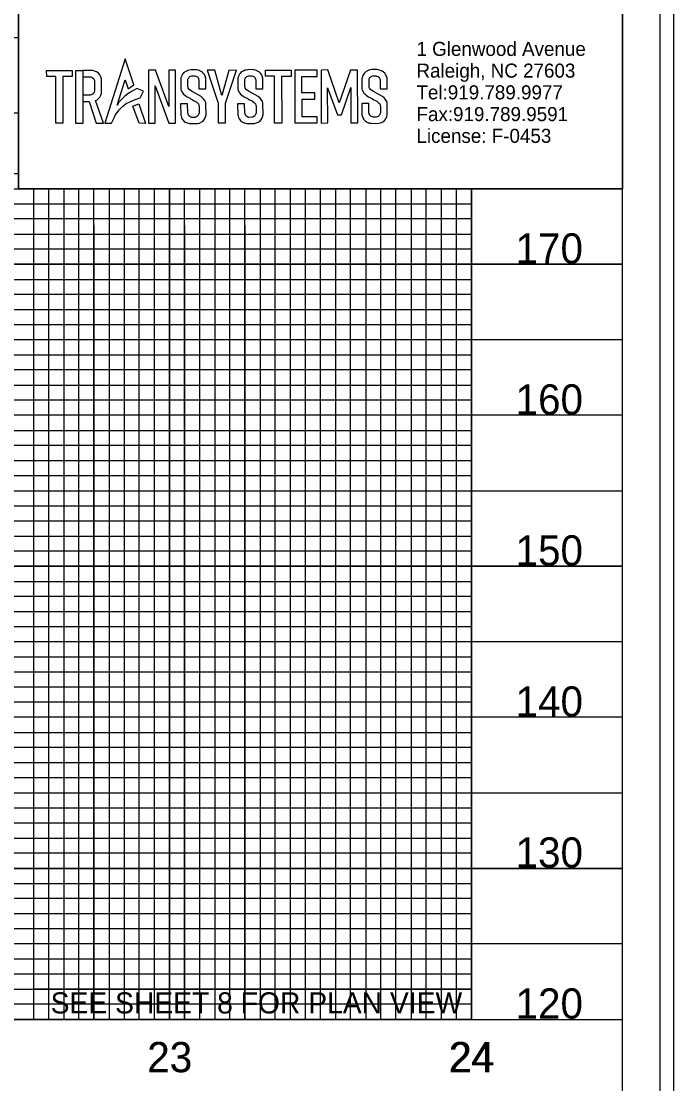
# Model space of a CAD drawing. Extents: x 1779926 to 1781610, y 605564 to 621564.
# Drawn here: x 1781393.9 to 1781610, y 606117.9 to 606469.7 of the extents above; entities that cross this region are included whole.
import ezdxf

# ---------------------------------------------------------------- set-up
doc = ezdxf.new("R2010")
doc.units = 0
for name, color, linetype in [('Exist Vertical Profile Horizontal Axis Label Major', 7, 'Continuous'), ('Exist Vertical Profile Vertical Axis Label', 7, 'Continuous'), ('Old_Level_2', 7, 'Continuous'), ('Old_Level_58', 7, 'Continuous'), ('Prop DSN Text', 7, 'Continuous'), ('Prop Grid Mask', 7, 'Continuous'), ('Scratch_Level_0', 7, 'Continuous'), ('Sheet DOT Grid CELL', 7, 'Continuous'), ('Sheet Layout Profile Border Port 1', 7, 'Continuous'), ('Sheet Plot Border Inside CELL', 7, 'Continuous'), ('Sheet Plot Border Outside CELL', 7, 'Continuous'), ('Sheet Profile CELL', 7, 'Continuous'), ('Sheet Profile Grid Major CELL', 7, 'Continuous'), ('Sheet Profile Grid Middle CELL', 7, 'Continuous'), ('Sheet Profile Grid Minor CELL', 7, 'Continuous')]:
    doc.layers.add(name, color=color, linetype=linetype)

msp = doc.modelspace()

# ---------------------------------------------------------------- linework, layer by layer
at = {"layer": 'Old_Level_2'}
for points in [[(1781428.25, 606457.24), (1781421.58, 606435.9), (1781423.81, 606435.91), (1781424.15, 606436.75), (1781424.72, 606437.91), (1781425.03, 606438.54), (1781425.41, 606439.08), (1781425.93, 606439.84), (1781426.26, 606440.31), (1781426.64, 606440.7), (1781427.02, 606441.09), (1781427.51, 606441.59), (1781427.92, 606441.86), (1781428.33, 606442.19), (1781428.89, 606442.51), (1781429.38, 606442.79), (1781430.6, 606443.36), (1781431.6, 606443.77), (1781433.24, 606444.33), (1781434.38, 606446.47), (1781432.2, 606447.43), (1781430.57, 606446.54), (1781429.19, 606445.64), (1781428.21, 606444.84), (1781427.69, 606444.42), (1781427.15, 606443.85), (1781426.62, 606443.28), (1781426.22, 606442.86), (1781425.84, 606442.21), (1781425.63, 606441.85), (1781428.26, 606450.23), (1781429.26, 606447.34), (1781431.16, 606448.59)], [(1781402.29, 606453.39), (1781410.75, 606453.4), (1781410.75, 606451.32), (1781407.64, 606451.32), (1781407.66, 606435.9), (1781405.31, 606435.9), (1781405.29, 606451.42), (1781402.32, 606451.42)], [(1781411.91, 606453.38), (1781414.22, 606453.39), (1781414.24, 606435.82), (1781411.92, 606435.82)], [(1781414.22, 606451.3), (1781416.61, 606451.3), (1781416.91, 606451.25), (1781417.32, 606451.09), (1781417.64, 606450.87), (1781417.87, 606450.6), (1781418.03, 606450.27), (1781418.15, 606450.01), (1781418.15, 606449.43), (1781418.16, 606446.94), (1781418.1, 606446.61), (1781418.01, 606446.17), (1781417.88, 606445.87), (1781417.68, 606445.61), (1781417.41, 606445.4), (1781416.99, 606445.25), (1781416.66, 606445.2), (1781416.34, 606445.16), (1781414.23, 606445.15), (1781414.24, 606443.04), (1781416.35, 606443.06), (1781418.72, 606435.89), (1781421.13, 606435.92), (1781418.48, 606443.46), (1781418.86, 606443.59), (1781419.4, 606443.99), (1781419.89, 606444.53), (1781420.23, 606445.16), (1781420.45, 606445.79), (1781420.43, 606445.98), (1781420.48, 606450.54), (1781420.27, 606451.29), (1781419.91, 606451.97), (1781419.5, 606452.44), (1781418.8, 606452.91), (1781418.12, 606453.14), (1781417.45, 606453.36), (1781417.04, 606453.36), (1781414.22, 606453.39)], [(1781436.02, 606453.42), (1781436.03, 606435.96), (1781438.27, 606435.96), (1781438.26, 606448.24), (1781442.71, 606435.94), (1781444.96, 606435.97), (1781444.94, 606453.47), (1781442.76, 606453.47), (1781442.78, 606441.49), (1781438.37, 606453.43)], [(1781452.72, 606447.25), (1781455.03, 606447.25), (1781455.02, 606450.73), (1781454.83, 606451.43), (1781454.55, 606452.02), (1781454.25, 606452.41), (1781453.88, 606452.77), (1781453.44, 606453.05), (1781453.01, 606453.22), (1781453.01, 606453.22), (1781452.55, 606453.42), (1781452.07, 606453.54), (1781451.75, 606453.62), (1781450, 606453.58), (1781449.47, 606453.49), (1781449.02, 606453.41), (1781448.55, 606453.17), (1781448.15, 606452.96), (1781447.76, 606452.68), (1781447.45, 606452.36), (1781447.2, 606452), (1781447.01, 606451.6), (1781446.75, 606450.91), (1781446.7, 606450.39), (1781446.7, 606447.22), (1781446.82, 606446.75), (1781447.05, 606446.25), (1781447.34, 606445.84), (1781447.63, 606445.53), (1781448.08, 606445.18), (1781448.54, 606444.84), (1781448.82, 606444.62), (1781449.3, 606444.39), (1781449.79, 606444.17), (1781450.18, 606443.91), (1781450.62, 606443.63), (1781451.15, 606443.36), (1781451.58, 606443.14), (1781452.01, 606442.83), (1781452.32, 606442.53), (1781452.57, 606442.29), (1781452.72, 606441.81), (1781452.82, 606441.51), (1781452.78, 606439.28), (1781452.62, 606438.79), (1781452.38, 606438.37), (1781452.05, 606438.08), (1781451.69, 606437.92), (1781451.35, 606437.85), (1781450.39, 606437.83), (1781450.07, 606437.92), (1781449.74, 606438.11), (1781449.41, 606438.31), (1781449.27, 606438.64), (1781449.13, 606438.98), (1781449.01, 606439.24), (1781448.98, 606442.36), (1781446.64, 606442.33), (1781446.68, 606438.62), (1781446.8, 606438.34), (1781447.07, 606437.47), (1781447.24, 606437.18), (1781447.5, 606436.86), (1781447.88, 606436.49), (1781448.18, 606436.3), (1781448.62, 606436.11), (1781448.78, 606436.05), (1781449.2, 606435.87), (1781449.74, 606435.81), (1781450.13, 606435.77), (1781452.27, 606435.83), (1781452.87, 606435.97), (1781453.69, 606436.34), (1781453.97, 606436.47), (1781454.6, 606437.26), (1781454.93, 606438.05), (1781455.08, 606438.76), (1781455.03, 606442.18), (1781455.02, 606442.65), (1781454.89, 606443.03), (1781454.7, 606443.38), (1781454.16, 606444.14), (1781453.45, 606444.7), (1781452.48, 606445.28), (1781451.73, 606445.72), (1781450.27, 606446.49), (1781449.52, 606447.05), (1781449.19, 606447.47), (1781449.11, 606447.75), (1781449.03, 606448.04), (1781449.08, 606450.47), (1781449.2, 606450.72), (1781449.33, 606450.98), (1781449.51, 606451.13), (1781449.74, 606451.33), (1781450, 606451.43), (1781450.25, 606451.54), (1781450.4, 606451.51), (1781450.42, 606451.59), (1781451.38, 606451.57), (1781451.65, 606451.46), (1781451.93, 606451.35), (1781452.21, 606451.24), (1781452.34, 606451.05), (1781452.52, 606450.77), (1781452.61, 606450.49), (1781452.71, 606450.22), (1781452.7, 606449.91)], [(1781457.99, 606453.43), (1781455.45, 606453.43), (1781459.07, 606442.55), (1781459.1, 606436), (1781461.49, 606436.02), (1781461.46, 606442.51), (1781465.12, 606453.47), (1781462.62, 606453.4), (1781460.31, 606445.06)], [(1781471.59, 606447.27), (1781473.9, 606447.27), (1781473.89, 606450.75), (1781473.7, 606451.45), (1781473.42, 606452.04), (1781473.12, 606452.43), (1781472.75, 606452.78), (1781472.31, 606453.07), (1781471.88, 606453.24), (1781471.88, 606453.24), (1781471.43, 606453.43), (1781470.94, 606453.56), (1781470.62, 606453.64), (1781468.87, 606453.6), (1781468.34, 606453.51), (1781467.89, 606453.43), (1781467.43, 606453.19), (1781467.02, 606452.98), (1781466.63, 606452.69), (1781466.32, 606452.38), (1781466.08, 606452.02), (1781465.88, 606451.62), (1781465.63, 606450.92), (1781465.58, 606450.41), (1781465.58, 606447.24), (1781465.69, 606446.76), (1781465.92, 606446.27), (1781466.21, 606445.86), (1781466.51, 606445.55), (1781466.96, 606445.2), (1781467.41, 606444.85), (1781467.69, 606444.63), (1781468.18, 606444.41), (1781468.66, 606444.18), (1781469.05, 606443.93), (1781469.49, 606443.64), (1781470.02, 606443.38), (1781470.45, 606443.16), (1781470.88, 606442.84), (1781471.19, 606442.55), (1781471.44, 606442.31), (1781471.59, 606441.83), (1781471.69, 606441.53), (1781471.65, 606439.29), (1781471.49, 606438.81), (1781471.25, 606438.39), (1781470.92, 606438.1), (1781470.56, 606437.94), (1781470.22, 606437.87), (1781469.26, 606437.85), (1781468.94, 606437.94), (1781468.61, 606438.13), (1781468.28, 606438.32), (1781468.14, 606438.66), (1781468, 606438.99), (1781467.88, 606439.26), (1781467.85, 606442.37), (1781465.51, 606442.35), (1781465.55, 606438.64), (1781465.67, 606438.35), (1781465.94, 606437.49), (1781466.12, 606437.2), (1781466.37, 606436.88), (1781466.75, 606436.51), (1781467.05, 606436.31), (1781467.49, 606436.13), (1781467.65, 606436.06), (1781468.08, 606435.88), (1781468.61, 606435.83), (1781469, 606435.79), (1781471.15, 606435.84), (1781471.74, 606435.99), (1781472.57, 606436.36), (1781472.85, 606436.49), (1781473.47, 606437.28), (1781473.8, 606438.06), (1781473.96, 606438.77), (1781473.9, 606442.2), (1781473.9, 606442.67), (1781473.76, 606443.04), (1781473.57, 606443.4), (1781473.03, 606444.16), (1781472.33, 606444.71), (1781471.35, 606445.29), (1781470.61, 606445.74), (1781469.14, 606446.5), (1781468.39, 606447.07), (1781468.06, 606447.49), (1781467.98, 606447.77), (1781467.91, 606448.06), (1781467.95, 606450.49), (1781468.08, 606450.74), (1781468.2, 606451), (1781468.38, 606451.15), (1781468.61, 606451.34), (1781468.87, 606451.45), (1781469.13, 606451.56), (1781469.27, 606451.53), (1781469.29, 606451.6), (1781470.25, 606451.59), (1781470.52, 606451.48), (1781470.8, 606451.37), (1781471.08, 606451.26), (1781471.21, 606451.07), (1781471.39, 606450.79), (1781471.49, 606450.51), (1781471.58, 606450.24), (1781471.57, 606449.93)], [(1781474.74, 606453.46), (1781483.21, 606453.46), (1781483.21, 606451.39), (1781480.1, 606451.39), (1781480.12, 606435.97), (1781477.77, 606435.96), (1781477.75, 606451.49), (1781474.78, 606451.49)], [(1781491.82, 606453.46), (1781484.43, 606453.46), (1781484.45, 606436.03), (1781491.92, 606436.04), (1781491.92, 606438.01), (1781486.87, 606438), (1781486.87, 606443.85), (1781491.08, 606443.85), (1781491.08, 606445.92), (1781486.83, 606445.92), (1781486.83, 606451.42), (1781491.84, 606451.42)], [(1781499.19, 606442.61), (1781495.38, 606453.54), (1781493.17, 606453.43), (1781493.25, 606435.97), (1781495.36, 606435.98), (1781495.31, 606447.66), (1781498.57, 606438.67), (1781499.92, 606438.64), (1781502.99, 606447.77), (1781503.03, 606436.05), (1781505.32, 606436.06), (1781505.25, 606453.48), (1781502.95, 606453.47)], [(1781512.72, 606447.31), (1781515.03, 606447.31), (1781515.03, 606450.78), (1781514.83, 606451.49), (1781514.55, 606452.08), (1781514.25, 606452.47), (1781513.88, 606452.82), (1781513.44, 606453.1), (1781513.02, 606453.28), (1781513.02, 606453.28), (1781512.56, 606453.47), (1781512.08, 606453.59), (1781511.76, 606453.67), (1781510.01, 606453.64), (1781509.48, 606453.55), (1781509.02, 606453.47), (1781508.56, 606453.23), (1781508.15, 606453.02), (1781507.76, 606452.73), (1781507.45, 606452.42), (1781507.21, 606452.05), (1781507.01, 606451.66), (1781506.76, 606450.96), (1781506.71, 606450.45), (1781506.71, 606447.28), (1781506.82, 606446.8), (1781507.05, 606446.31), (1781507.34, 606445.9), (1781507.64, 606445.59), (1781508.09, 606445.24), (1781508.54, 606444.89), (1781508.83, 606444.67), (1781509.31, 606444.45), (1781509.79, 606444.22), (1781510.18, 606443.97), (1781510.62, 606443.68), (1781511.15, 606443.42), (1781511.58, 606443.2), (1781512.01, 606442.88), (1781512.32, 606442.59), (1781512.57, 606442.35), (1781512.73, 606441.87), (1781512.82, 606441.57), (1781512.79, 606439.33), (1781512.62, 606438.85), (1781512.38, 606438.43), (1781512.05, 606438.14), (1781511.7, 606437.98), (1781511.36, 606437.91), (1781510.39, 606437.89), (1781510.07, 606437.98), (1781509.74, 606438.17), (1781509.41, 606438.36), (1781509.27, 606438.7), (1781509.13, 606439.03), (1781509.02, 606439.3), (1781508.98, 606442.41), (1781506.64, 606442.38), (1781506.69, 606438.67), (1781506.8, 606438.39), (1781507.07, 606437.53), (1781507.25, 606437.24), (1781507.5, 606436.92), (1781507.88, 606436.54), (1781508.19, 606436.35), (1781508.62, 606436.17), (1781508.78, 606436.1), (1781509.21, 606435.92), (1781509.74, 606435.87), (1781510.14, 606435.83), (1781512.28, 606435.88), (1781512.87, 606436.02), (1781513.7, 606436.4), (1781513.98, 606436.52), (1781514.6, 606437.32), (1781514.93, 606438.1), (1781515.09, 606438.81), (1781515.04, 606442.23), (1781515.03, 606442.71), (1781514.9, 606443.08), (1781514.71, 606443.44), (1781514.17, 606444.2), (1781513.46, 606444.75), (1781512.48, 606445.33), (1781511.74, 606445.78), (1781510.28, 606446.54), (1781509.52, 606447.1), (1781509.19, 606447.53), (1781509.12, 606447.81), (1781509.04, 606448.09), (1781509.08, 606450.52), (1781509.21, 606450.78), (1781509.33, 606451.03), (1781509.51, 606451.19), (1781509.74, 606451.38), (1781510, 606451.49), (1781510.26, 606451.6), (1781510.41, 606451.57), (1781510.42, 606451.64), (1781511.38, 606451.63), (1781511.66, 606451.52), (1781511.93, 606451.41), (1781512.21, 606451.3), (1781512.34, 606451.1), (1781512.53, 606450.83), (1781512.62, 606450.55), (1781512.71, 606450.27), (1781512.7, 606449.97)], [(1781430.86, 606441.53), (1781432.78, 606442.3), (1781435.04, 606435.86), (1781432.94, 606435.94)]]:
    msp.add_lwpolyline(points, close=True, dxfattribs=at)
at = {"layer": 'Old_Level_58'}
msp.add_lwpolyline([(1781392.96, 606478.15), (1781592.95, 606478.15), (1781592.95, 606414.2), (1781392.96, 606414.2)], close=True, dxfattribs=at)
at = {"layer": 'Prop Grid Mask'}
msp.add_lwpolyline([(1781542.96, 606149.2), (1781397.96, 606149.2), (1781397.96, 606139.2), (1781542.96, 606139.2)], close=True, dxfattribs=at)
at = {"layer": 'Scratch_Level_0'}
msp.add_lwpolyline([(1780142.96, 606139.19), (1780142.96, 606639.19), (1781392.96, 606639.19), (1781392.96, 606414.19), (1781542.96, 606414.19), (1781542.96, 606139.19)], close=True, dxfattribs=at)
at = {"layer": 'Sheet DOT Grid CELL'}
for p, q in [((1781442.96, 606139.2), (1781442.96, 606414.2)), ((1781492.96, 606139.2), (1781492.96, 606414.2)), ((1781542.96, 606139.2), (1781542.96, 606414.2)), ((1781592.96, 606389.2), (1780092.96, 606389.2)), ((1781592.96, 606339.2), (1780092.96, 606339.2)), ((1781592.96, 606289.2), (1780092.96, 606289.2)), ((1781592.96, 606239.2), (1780092.96, 606239.2)), ((1781592.96, 606189.2), (1780092.96, 606189.2))]:
    msp.add_line(p, q, dxfattribs=at)
at = {"layer": 'Sheet Layout Profile Border Port 1'}
msp.add_lwpolyline([(1780142.96, 606639.19), (1781392.91, 606639.2), (1781392.9, 606414.2), (1781542.96, 606414.19), (1781542.96, 606139.2), (1780142.96, 606139.19)], close=True, dxfattribs=at)
msp.add_lwpolyline([(1780142.96, 606478.15), (1780142.96, 606139.2), (1781542.96, 606139.2), (1781542.96, 606414.2)], dxfattribs=at)
at = {"layer": 'Sheet Plot Border Inside CELL'}
msp.add_lwpolyline([(1779938.96, 605586.65), (1781605.46, 605586.65), (1781605.46, 606641.75), (1779938.96, 606641.75)], close=True, dxfattribs=at)
at = {"layer": 'Sheet Plot Border Outside CELL'}
msp.add_lwpolyline([(1779925.96, 605564.2), (1781609.96, 605564.2), (1781609.96, 606664.2), (1779925.96, 606664.2)], close=True, dxfattribs=at)
at = {"layer": 'Sheet Profile CELL'}
msp.add_line((1780092.96, 606139.2), (1781592.96, 606139.2), dxfattribs=at)
msp.add_lwpolyline([(1781592.96, 606639.2), (1780092.96, 606639.2), (1780092.96, 605589.2), (1781592.96, 605589.2)], close=True, dxfattribs=at)
at = {"layer": 'Sheet Profile Grid Major CELL'}
for points in [[(1781542.96, 606414.2), (1781542.96, 606139.2), (1781592.96, 606139.2), (1781592.96, 606489.2)], [(1781392.91, 606439.2), (1780092.96, 606439.2), (1780092.96, 606389.2), (1781592.96, 606389.2)], [(1781442.96, 606414.2), (1781442.96, 606139.2), (1781492.96, 606139.2), (1781492.96, 606139.2), (1781492.96, 606414.2)], [(1781592.96, 606339.2), (1780092.96, 606339.2), (1780092.96, 606289.2), (1781592.96, 606289.2)], [(1781592.96, 606239.2), (1780092.96, 606239.2), (1780092.96, 606239.2), (1780092.96, 606189.2), (1781592.96, 606189.2)]]:
    msp.add_lwpolyline(points, dxfattribs=at)
at = {"layer": 'Sheet Profile Grid Middle CELL'}
for points in [[(1780917.96, 606639.2), (1780967.96, 606639.2), (1780967.96, 606139.2), (1781017.96, 606139.2), (1781017.96, 606639.2), (1781067.96, 606639.2), (1781067.96, 606139.2), (1781117.96, 606139.2), (1781117.96, 606639.2), (1781167.96, 606639.2), (1781167.96, 606139.2), (1781217.96, 606139.2), (1781217.96, 606639.2), (1781267.96, 606639.2), (1781267.96, 606139.2), (1781317.96, 606139.2), (1781317.96, 606639.2), (1781367.96, 606639.2), (1781367.96, 606139.2), (1781417.96, 606139.2), (1781417.96, 606414.2)], [(1781392.91, 606464.2), (1780092.96, 606464.2), (1780092.96, 606414.2), (1781417.96, 606414.2)], [(1781417.96, 606414.2), (1781592.96, 606414.2)], [(1781417.96, 606402), (1781417.96, 606139.2), (1781467.96, 606139.2), (1781467.96, 606414.2)], [(1781467.96, 606402), (1781467.96, 606139.2), (1781517.96, 606139.2), (1781517.96, 606414.2)], [(1781592.96, 606364.2), (1780092.96, 606364.2), (1780092.96, 606314.2), (1781592.96, 606314.2)], [(1781592.96, 606264.2), (1780092.96, 606264.2), (1780092.96, 606214.2), (1781592.96, 606214.2)], [(1781592.96, 606164.2), (1780092.96, 606164.2)]]:
    msp.add_lwpolyline(points, dxfattribs=at)
at = {"layer": 'Sheet Profile Grid Minor CELL'}
for p, q in [((1781542.96, 606404.2), (1780142.96, 606404.2)), ((1780142.96, 606399.2), (1781542.96, 606399.2)), ((1781542.96, 606394.2), (1780142.96, 606394.2)), ((1780142.96, 606384.2), (1781542.96, 606384.2)), ((1781542.96, 606379.2), (1780142.96, 606379.2)), ((1780142.96, 606374.2), (1781542.96, 606374.2)), ((1781542.96, 606369.2), (1780142.96, 606369.2)), ((1780142.96, 606359.2), (1781542.96, 606359.2)), ((1781542.96, 606354.2), (1780142.96, 606354.2)), ((1780142.96, 606349.2), (1781542.96, 606349.2)), ((1781542.96, 606344.2), (1780142.96, 606344.2)), ((1780142.96, 606334.2), (1781542.96, 606334.2)), ((1781542.96, 606329.2), (1780142.96, 606329.2)), ((1780142.96, 606324.2), (1781542.96, 606324.2)), ((1781542.96, 606319.2), (1780142.96, 606319.2)), ((1780142.96, 606309.2), (1781542.96, 606309.2)), ((1781542.96, 606304.2), (1780142.96, 606304.2)), ((1780142.96, 606299.2), (1781542.96, 606299.2)), ((1781542.96, 606294.2), (1780142.96, 606294.2)), ((1780142.96, 606284.2), (1781542.96, 606284.2)), ((1781542.96, 606279.2), (1780142.96, 606279.2)), ((1780142.96, 606274.2), (1781542.96, 606274.2)), ((1781542.96, 606269.2), (1780142.96, 606269.2)), ((1780142.96, 606259.2), (1781542.96, 606259.2)), ((1781542.96, 606254.2), (1780142.96, 606254.2)), ((1781542.96, 606249.2), (1780142.96, 606249.2)), ((1781542.96, 606244.2), (1780142.96, 606244.2)), ((1780142.96, 606234.2), (1781542.96, 606234.2)), ((1781542.96, 606229.2), (1780142.96, 606229.2)), ((1780142.96, 606224.2), (1781542.96, 606224.2)), ((1781542.96, 606219.2), (1780142.96, 606219.2)), ((1780142.96, 606209.2), (1781542.96, 606209.2)), ((1781542.96, 606204.2), (1780142.96, 606204.2)), ((1780142.96, 606199.2), (1781542.96, 606199.2)), ((1781542.96, 606194.2), (1780142.96, 606194.2)), ((1780142.96, 606184.2), (1781542.96, 606184.2)), ((1781542.96, 606179.2), (1780142.96, 606179.2)), ((1780142.96, 606174.2), (1781542.96, 606174.2)), ((1781542.96, 606169.2), (1780142.96, 606169.2)), ((1780142.96, 606159.2), (1781542.96, 606159.2)), ((1781542.96, 606154.2), (1780142.96, 606154.2)), ((1780142.96, 606149.2), (1781542.96, 606149.2))]:
    msp.add_line(p, q, dxfattribs=at)
for points in [[(1781392.91, 606419.2), (1780142.96, 606419.2), (1780142.96, 606409.2), (1781542.96, 606409.2)], [(1781397.96, 606414.2), (1781397.96, 606139.2), (1781402.96, 606139.2), (1781402.96, 606414.2)], [(1781407.96, 606414.2), (1781407.96, 606139.2), (1781412.96, 606139.2), (1781412.96, 606414.2)], [(1781422.96, 606414.2), (1781422.96, 606139.2), (1781422.96, 606139.2), (1781427.96, 606139.2), (1781432.96, 606139.2), (1781432.96, 606414.2)], [(1781427.96, 606414.2), (1781427.96, 606139.2)], [(1781437.94, 606414.2), (1781437.86, 606139.25), (1781442.86, 606139.25), (1781447.96, 606139.2), (1781447.96, 606414.2)], [(1781447.96, 606402), (1781447.96, 606139.2), (1781452.96, 606139.2), (1781452.96, 606414.2)], [(1781457.96, 606414.2), (1781457.96, 606139.2), (1781462.96, 606139.2), (1781462.96, 606414.2)], [(1781472.96, 606414.2), (1781472.96, 606139.2), (1781477.96, 606139.2), (1781477.96, 606414.2)], [(1781482.96, 606414.2), (1781482.96, 606139.2), (1781487.96, 606139.2), (1781487.96, 606414.2)], [(1781497.96, 606414.2), (1781497.96, 606139.2), (1781502.96, 606139.2), (1781502.96, 606414.2)], [(1781507.96, 606414.2), (1781507.96, 606139.2), (1781512.96, 606139.2), (1781512.96, 606414.2)], [(1781522.96, 606414.2), (1781522.96, 606139.2), (1781527.96, 606139.2), (1781527.96, 606414.2)], [(1781532.96, 606414.2), (1781532.96, 606139.2), (1781537.96, 606139.2), (1781537.96, 606414.2)], [(1781542.96, 606144.2), (1780142.96, 606144.2)]]:
    msp.add_lwpolyline(points, dxfattribs=at)

# ---------------------------------------------------------------- texts
at = {"layer": 'Exist Vertical Profile Horizontal Axis Label Major'}
for s, p in [('23', (1781435.57, 606121.7)), ('23', (1781435.63, 606121.7)), ('23', (1781435.63, 606121.7)), ('24', (1781535.41, 606121.7)), ('24', (1781535.69, 606121.7)), ('24', (1781535.69, 606121.7))]:
    msp.add_text(s, height=10, dxfattribs=at).set_placement(p)
at = {"layer": 'Exist Vertical Profile Vertical Axis Label'}
for s, p in [('170', (1781557.59, 606389.45)), ('160', (1781557.59, 606339.45)), ('150', (1781557.59, 606289.45)), ('140', (1781557.59, 606239.45)), ('130', (1781557.59, 606189.45)), ('120', (1781557.59, 606139.45))]:
    msp.add_text(s, height=10, dxfattribs=at).set_placement(p)
at = {"layer": 'Old_Level_2'}
for s, p in [('1 Glenwood Avenue', (1781524.75, 606458.19)), ('Raleigh, NC 27603', (1781524.75, 606450.99)), ('Tel:919.789.9977 ', (1781524.75, 606443.8)), ('Fax:919.789.9591', (1781524.75, 606436.6)), ('License: F-0453', (1781524.75, 606429.4))]:
    msp.add_text(s, height=4.6576, rotation=360, dxfattribs=at).set_placement(p)
at = {"layer": 'Prop DSN Text'}
msp.add_text('SEE SHEET 8 FOR PLAN VIEW', height=7, dxfattribs=at).set_placement((1781403.61, 606141.15))

doc.saveas('drawing.dxf')
